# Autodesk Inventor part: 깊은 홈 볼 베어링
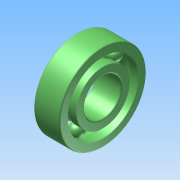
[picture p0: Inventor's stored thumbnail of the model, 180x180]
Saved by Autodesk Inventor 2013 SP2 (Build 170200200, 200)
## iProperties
Created: 2026-07
Part Number: 깊은 홈 볼 베어링
Material: Generic
Document SubType Name: Modeling
Designer: aa
Density: 1 g/cm^3
변환 표준: STEP AP214IS
전처리기: Build: 200, Release: 2013 SP2 Update 6 - Date: Thu 07/17/2014
전송 단위: 밀리미터
불확실성: 0.01
Author: aa
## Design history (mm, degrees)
node "깊은 홈 볼 베어링 62031"
body "Solid1"
node "Solid1_1"
node "Solid1_2"
node "Solid1_3"
node "Solid1_4"
node "Solid1_5"
node "Solid1_6"
node "Solid1_7"
node "Solid1_8"
node "기준1"
node "기준2"
node "기준3"
node "기준4"
node "기준5"
node "기준6"
node "기준7"
node "기준8"
node "기준9"
